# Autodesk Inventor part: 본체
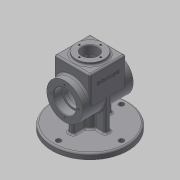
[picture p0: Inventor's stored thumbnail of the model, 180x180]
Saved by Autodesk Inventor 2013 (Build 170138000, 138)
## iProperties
Created: 2020-07
Part Number: 본체
Material: 알루미늄 6061
Document SubType Name: Modeling
Designer: mduedu
Density: 2.71 g/cm^3
Author: mduedu
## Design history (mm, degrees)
sketch "스케치1"
  geometry: C1 r 32 at (0, 0); 1 further point
  constraints: 1 centre point, 1 coincident
  dimensions: "d0" = 64 diameter of C1
extrude "돌출1" new body sketch "스케치1" stored distance "d1" = 90; taper "d2" = 0 deg
sketch "스케치3"
  geometry: L1 (0, -32)-(50, -32); L2 (50, -32)-(50, 32); L3 (50, 32)-(0, 32); L4 (0, 32)-(0, -32); C1 r 32 at (0, 0) reference; 2 further points
  constraints: 8 end point, 2 parallel, 1 coincident, 1 horizontal, 1 midpoint, 1 perpendicular, 1 tangent
  dimensions: "d5" = 50 distance of L2.end L3.end
extrude "돌출2" join sketch "스케치3" stored distance "d7" = 64; taper "d8" = 0 deg
sketch "스케치4"
  geometry: C1 r 25 at (32, 32); 1 further point
  constraints: 1 centre point, 1 coincident
  dimensions: "d9" = 50 diameter of C1
extrude "돌출3" join sketch "스케치4" distance "d10" = 5; taper "d11" = 0 deg
sketch "스케치5"
  geometry: L1 (0, -25)-(40, -25); L2 (40, -25)-(40, 25); L3 (40, 25)-(0, 25); L4 (0, 25)-(0, -25); L5 (55, -25)-(55, 25) reference; A1 r 25 centre (0, 0) between (0, 25) and (0, -25); A2 r 25 centre (0, 0) between (0, -25) and (0, 25); 2 further points
  constraints: 8 end point, 4 point on circle, 2 centre point, 2 coincident, 2 parallel, 1 horizontal, 1 midpoint, 1 perpendicular, 1 tangent
  dimensions: "d12" = 50 diameter of A1; "d13" = 15 distance between parallel lines of L2 L5
extrude "돌출4" cut sketch "스케치5" stored distance "d14" = 48; taper "d15" = 0 deg
sketch "스케치6"
  geometry: C1 r 20 at (0, 0); 1 further point
  constraints: 1 centre point, 1 coincident
  dimensions: "d16" = 40 diameter of C1
extrude "돌출5" cut sketch "스케치6" distance "d17" = 15; taper "d18" = 0 deg
sketch "스케치7"
  geometry: C1 r 17 at (0, 0); 1 further point
  constraints: 1 centre point, 1 coincident
  dimensions: "d19" = 34 diameter of C1
extrude "돌출6" cut sketch "스케치7" stored distance "d20" = 15; taper "d21" = 0 deg
fillet "모깎기1" dims "d22" = 3
fillet "모깎기2" dims "d23" = 3
fillet "모깎기3" dims "d24" = 3
fillet "모깎기4" dims "d25" = 3
fillet "모깎기5" dims "d26" = 3
sketch "스케치8"
  geometry: C1 r 14 at (0, 0); 1 further point
  constraints: 1 centre point, 1 coincident
  dimensions: "d27" = 28 diameter of C1
extrude "돌출7" cut sketch "스케치8" stored distance "d28" = 15; taper "d29" = 0 deg
node "작업 평면1"
sketch "스케치9"
  geometry: C1 r 67.5 at (0, 0); 1 further point
  constraints: 1 centre point, 1 coincident
  dimensions: "d31" = 135 diameter of C1
extrude "돌출8" join sketch "스케치9" distance "d33" = 10; taper "d34" = 0 deg
sketch "스케치10"
  geometry: C1 r 15 at (0, 0); 1 further point
  constraints: 1 centre point, 1 coincident
  dimensions: "d35" = 30 diameter of C1
extrude "돌출9" join sketch "스케치10" stored distance "d39" = 10; taper "d40" = 0 deg
sketch "스케치11"
  geometry: L1 (-35, -5)-(35, -5); L2 (35, -5)-(35, 5); L3 (35, 5)-(-35, 5); L4 (-35, 5)-(-35, -5); L5 (-35, -5)-(35, 5); L6 (35, -5)-(-35, 5); 1 further point
  constraints: 12 end point, 2 midpoint, 2 parallel, 1 horizontal, 1 perpendicular
  dimensions: "d41" = 70 distance of L3.end L2.end; "d42" = 10 distance of L2.end L1.end
extrude "돌출10" join sketch "스케치11" stored distance "d43" = 10; taper "d44" = 0 deg
sketch "스케치12"
  geometry: L1 (-5, -32)-(5, -32); L2 (5, -32)-(5, 32); L3 (5, 32)-(-5, 32); L4 (-5, 32)-(-5, -32); L5 (-5, -32)-(5, 32); L6 (5, -32)-(-5, 32); 1 further point
  constraints: 12 end point, 2 midpoint, 2 parallel, 1 horizontal, 1 perpendicular
  dimensions: "d45" = 10 distance of L3.end L2.end; "d46" = 64 distance of L2.end L1.end
extrude "돌출11" join sketch "스케치12" stored distance "d47" = 10; taper "d48" = 0 deg
fillet "모깎기6" dims "d50" = 3
fillet "모깎기7" dims "d51" = 3
sketch "스케치13" dims "d52" = 112
  geometry: 3 further points
  constraints: 2 horizontal alignment, 1 coincident, 2 other
hole "구멍1" sketch "스케치13" at (-56, 0) diameter "d54" = 9; stored, may be unused: countersink angle "d58" = 90 deg, drill point angle "d60" = 118 deg; dims "d55" = 6, "d56" = 4, "d57" = 2, "d59" = 8
fillet "모깎기8" dims "d64" = 3
sketch "스케치14" dims "d67" = 50
  geometry: 3 further points
  constraints: 2 vertical alignment, 1 coincident, 2 other
hole "구멍2" sketch "스케치14" at (0, 25) diameter "d68" = 3.242; stored, may be unused: countersink angle "d72" = 90 deg, drill point angle "d74" = 118 deg; dims "d69" = 7, "d70" = 4, "d71" = 2, "d73" = 9
sketch "스케치15" dims "d78" = 38
  geometry: 3 further points
  constraints: 2 vertical alignment, 1 coincident, 2 other
hole "구멍3" sketch "스케치15" at (0, 19) diameter "d79" = 3.242; stored, may be unused: countersink angle "d83" = 90 deg, drill point angle "d85" = 118 deg; dims "d80" = 8, "d81" = 4, "d82" = 2, "d84" = 10
fillet "모깎기9" dims "d89" = 0.3
chamfer "모따기1" distance "d90" = 1; stored, may be unused: second distance "d91" = 2, angle "d92" = 45 deg
chamfer "모따기2" distance "d93" = 1; stored, may be unused: second distance "d94" = 2, angle "d95" = 45 deg
sketch "스케치16"
  geometry: L1 (-3, 0)-(-3, -27.404) reference; L2 (54, 8)-(4, 8) reference; 2 further points
  constraints: 1 other
  dimensions: "d96" = 32 distance from line of point (29, -17) L1; "d97" = 25 distance from line of point (29, -17) L2
feature "엠보싱1" sketch "스케치16" dims "d0" = 64, "d98" = 0.5, "d99" = 0
node "솔리드1"
mirror "대칭1"
pattern_circular "원형 패턴1" dims angle "d62" = 360 deg
pattern_circular "원형 패턴2" dims angle "d76" = 360 deg
mirror "대칭2"
pattern_circular "원형 패턴3" dims angle "d87" = 360 deg
other parameters: "d30" = -65
